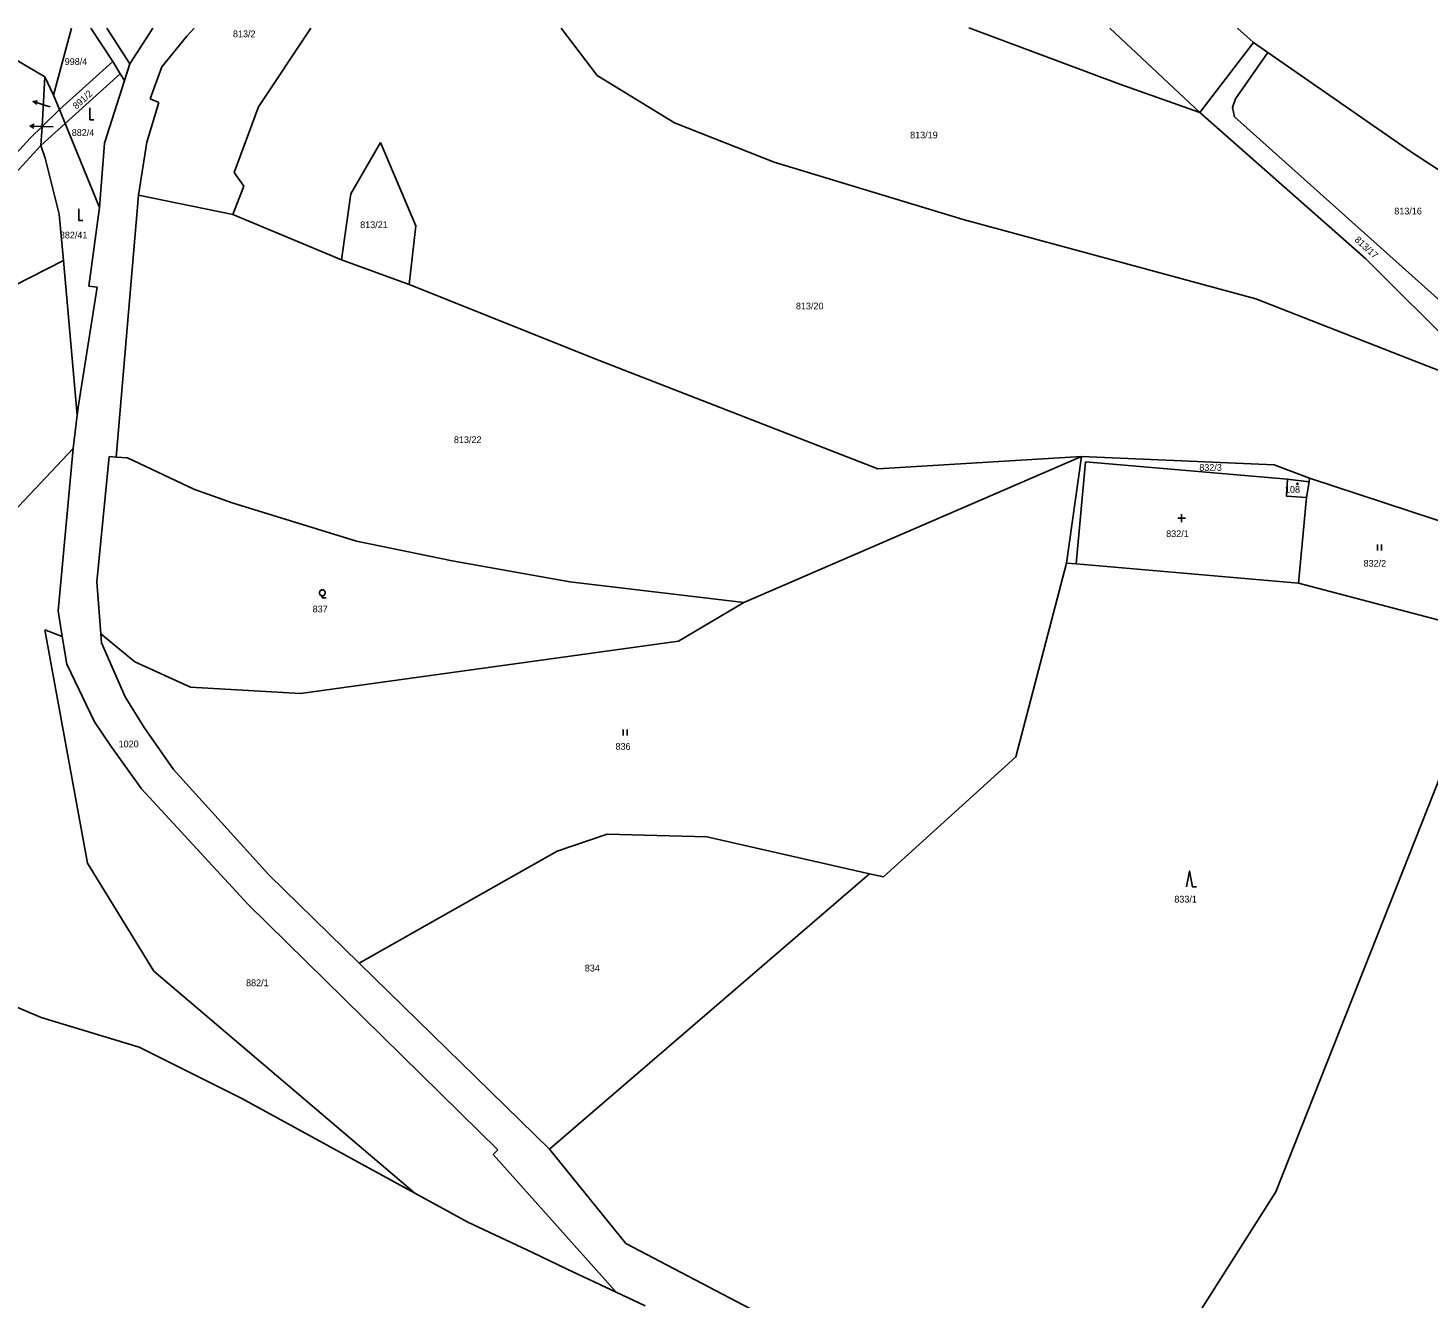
# Model space of a CAD drawing. Extents: x -801907 to -800293, y -1016964 to -1015684.
# Drawn here: x -801659.6 to -801306.6, y -1016005.6 to -1015685.2 of the extents above; entities that cross this region are included whole.
import ezdxf

# ---------------------------------------------------------------- set-up
doc = ezdxf.new("R2010")
doc.units = 0
for name, color, linetype in [('Default', 7, 'Continuous'), ('KN_HRANICE', 7, 'Continuous'), ('KN_KULTURY', 7, 'Continuous'), ('KN_PARCELY', 7, 'Continuous')]:
    doc.layers.add(name, color=color, linetype=linetype)

# ---------------------------------------------------------------- blocks, each defined once
blk = doc.blocks.new('302')
at = {"layer": 'Default'}
blk.add_lwpolyline([(0, 3), (0, 0), (1, 0)], dxfattribs=at)
blk = doc.blocks.new('305')
at = {"layer": 'Default'}
blk.add_lwpolyline([(0, 0.53), (-0.19, 0.53), (-0.53, 0.72), (-0.72, 1.06), (-0.72, 1.45), (-0.53, 1.79), (-0.19, 1.98), (0.2, 1.98), (0.54, 1.79), (0.73, 1.45), (0.73, 1.06), (0.54, 0.72), (0.2, 0.53), (0.01, 0.53), (0.01, 0), (1.01, 0)], dxfattribs=at)
blk = doc.blocks.new('306')
at = {"layer": 'Default'}
for p, q in [((-0.5, 1.5), (-0.5, 0)), ((0.5, 0), (0.5, 1.5))]:
    blk.add_line(p, q, dxfattribs=at)
blk = doc.blocks.new('308')
at = {"layer": 'Default'}
blk.add_lwpolyline([(-0.75, 0), (0, 4), (0.75, 0), (1.75, 0)], dxfattribs=at)
blk = doc.blocks.new('315')
at = {"layer": 'Default'}
for p, q in [((-1, 1), (1, 1)), ((0, 0), (0, 2))]:
    blk.add_line(p, q, dxfattribs=at)
blk = doc.blocks.new('10292')
at = {"layer": 'Default'}
blk.add_line((0, 3), (0, 0), dxfattribs=at)
blk.add_lwpolyline([(-0.5, 2), (0, 3), (0.5, 2)], dxfattribs=at)
blk = doc.blocks.new('402')
at = {"layer": 'Default'}
blk.add_lwpolyline([(0.09, 0.15), (0.18, 0), (0.09, -0.15), (-0.09, -0.15), (-0.18, 0), (-0.09, 0.15), (0.09, 0.15)], dxfattribs=at)

msp = doc.modelspace()

# ---------------------------------------------------------------- linework, layer by layer
at = {"layer": 'KN_HRANICE'}
for p, q in [((-801655.35, -1015697.53), (-801676.32, -1015685.21)), ((-801648.62, -1015685.21), (-801653.16, -1015702.14)), ((-801638.19, -1015693.68), (-801643.75, -1015685.21)), ((-801639.75, -1015685.21), (-801633.9, -1015694.23)), ((-801628.12, -1015685.21), (-801633.9, -1015694.23)), ((-801619.55, -1015687.28), (-801617.68, -1015685.21)), ((-801601.48, -1015705.1), (-801588.3, -1015685.21)), ((-801516.12, -1015697.22), (-801525.13, -1015685.21)), ((-801422.39, -1015685.21), (-801422.14, -1015685.28)), ((-801422.14, -1015685.28), (-801384.58, -1015699.28)), ((-801386.82, -1015685.21), (-801364.15, -1015706.53)), ((-801350.63, -1015688.84), (-801354.65, -1015685.21)), ((-801625.84, -1015695.02), (-801619.55, -1015687.28)), ((-801364.15, -1015706.53), (-801350.63, -1015688.84)), ((-801350.63, -1015688.84), (-801347.01, -1015691.35)), ((-801355.17, -1015703.07), (-801347.01, -1015691.35)), ((-801347.01, -1015691.35), (-801311.03, -1015716.36)), ((-801638.19, -1015693.68), (-801651.68, -1015705.75)), ((-801636.37, -1015696.73), (-801638.19, -1015693.68)), ((-801633.9, -1015694.23), (-801635.25, -1015698.47)), ((-801628.81, -1015703.03), (-801625.84, -1015695.02)), ((-801656.05, -1015710.04), (-801655.35, -1015697.53)), ((-801655.35, -1015697.53), (-801653.16, -1015702.14)), ((-801650.23, -1015709.31), (-801636.37, -1015696.73)), ((-801635.25, -1015698.47), (-801640.27, -1015714.25)), ((-801636.37, -1015696.73), (-801635.25, -1015698.47)), ((-801496.58, -1015709.13), (-801516.12, -1015697.22)), ((-801384.58, -1015699.28), (-801364.15, -1015706.53)), ((-801653.16, -1015702.14), (-801651.68, -1015705.75)), ((-801626.56, -1015704.02), (-801628.81, -1015703.03)), ((-801355.93, -1015705.28), (-801355.17, -1015703.07)), ((-801656.05, -1015710.04), (-801651.68, -1015705.75)), ((-801651.68, -1015705.75), (-801650.23, -1015709.31)), ((-801629.63, -1015714.03), (-801626.56, -1015704.02)), ((-801607.64, -1015721.66), (-801601.48, -1015705.1)), ((-801364.15, -1015706.53), (-801322.27, -1015743.39)), ((-801355.45, -1015707.64), (-801355.93, -1015705.28)), ((-801658.98, -1015712.93), (-801656.05, -1015710.04)), ((-801656.31, -1015714.79), (-801650.23, -1015709.31)), ((-801656.31, -1015714.79), (-801656.05, -1015710.04)), ((-801650.23, -1015709.31), (-801641.58, -1015730.49)), ((-801471.47, -1015719.01), (-801496.58, -1015709.13)), ((-801278.86, -1015776.11), (-801355.45, -1015707.64)), ((-801680.63, -1015736.45), (-801658.98, -1015712.93)), ((-801677.9, -1015738.17), (-801656.31, -1015714.79)), ((-801656.31, -1015714.79), (-801655.26, -1015718.04)), ((-801640.27, -1015714.25), (-801641.58, -1015730.49)), ((-801631.69, -1015727.32), (-801629.63, -1015714.03)), ((-801578.23, -1015727.02), (-801570.69, -1015714.08)), ((-801570.69, -1015714.08), (-801561.77, -1015735.11)), ((-801265.47, -1015746.32), (-801311.03, -1015716.36)), ((-801655.26, -1015718.04), (-801651.72, -1015732.13)), ((-801423.84, -1015733.52), (-801471.47, -1015719.01)), ((-801605.16, -1015725.05), (-801607.64, -1015721.66)), ((-801637.38, -1015793.41), (-801631.69, -1015727.32)), ((-801631.69, -1015727.32), (-801607.98, -1015732.2)), ((-801607.98, -1015732.2), (-801605.16, -1015725.05)), ((-801580.58, -1015743.62), (-801578.23, -1015727.02)), ((-801641.58, -1015730.49), (-801644.24, -1015750.29)), ((-801651.72, -1015732.13), (-801650.62, -1015743.8)), ((-801607.98, -1015732.2), (-801580.58, -1015743.62)), ((-801561.77, -1015735.11), (-801563.47, -1015749.83)), ((-801350.07, -1015753.47), (-801423.84, -1015733.52)), ((-801650.62, -1015743.8), (-801699.52, -1015768.78)), ((-801650.62, -1015743.8), (-801647.16, -1015782.83)), ((-801580.58, -1015743.62), (-801563.47, -1015749.83)), ((-801322.27, -1015743.39), (-801287.84, -1015777.83)), ((-801642.16, -1015750.56), (-801646.85, -1015780.3)), ((-801644.24, -1015750.29), (-801642.16, -1015750.56)), ((-801563.47, -1015749.83), (-801515.35, -1015769.14)), ((-801311.64, -1015768.49), (-801350.07, -1015753.47)), ((-801515.35, -1015769.14), (-801445.36, -1015796.31)), ((-801287.84, -1015777.83), (-801311.64, -1015768.49)), ((-801646.85, -1015780.3), (-801647.16, -1015782.83)), ((-801647.16, -1015782.83), (-801648.17, -1015791.2)), ((-801648.17, -1015791.2), (-801670.98, -1015815.34)), ((-801648.17, -1015791.2), (-801651.99, -1015832.14)), ((-801642.25, -1015824.81), (-801639.09, -1015793.23)), ((-801639.09, -1015793.23), (-801637.38, -1015793.41)), ((-801637.38, -1015793.41), (-801634.52, -1015793.59)), ((-801634.52, -1015793.59), (-801617.79, -1015801.46)), ((-801393.97, -1015793.22), (-801479.12, -1015830.07)), ((-801393.97, -1015793.22), (-801445.36, -1015796.31)), ((-801393.97, -1015793.22), (-801397.76, -1015820.1)), ((-801395.31, -1015820.31), (-801392.98, -1015794.6)), ((-801345.43, -1015795.33), (-801393.97, -1015793.22)), ((-801392.98, -1015794.6), (-801342.06, -1015798.94)), ((-801336.48, -1015798.73), (-801345.43, -1015795.33)), ((-801617.79, -1015801.46), (-801608.15, -1015804.9)), ((-801342.06, -1015798.94), (-801336.61, -1015799.6)), ((-801336.61, -1015799.6), (-801337.22, -1015803.55)), ((-801336.61, -1015799.6), (-801336.48, -1015798.73)), ((-801336.48, -1015798.73), (-801290.84, -1015813.7)), ((-801608.15, -1015804.9), (-801576.8, -1015814.54)), ((-801337.22, -1015803.55), (-801339.25, -1015825.17)), ((-801576.8, -1015814.54), (-801552.64, -1015819.52)), ((-801552.64, -1015819.52), (-801522.96, -1015824.79)), ((-801397.76, -1015820.1), (-801410.54, -1015868.95)), ((-801397.76, -1015820.1), (-801395.31, -1015820.31)), ((-801339.25, -1015825.17), (-801395.31, -1015820.31)), ((-801641.26, -1015837.91), (-801642.25, -1015824.81)), ((-801522.96, -1015824.79), (-801479.12, -1015830.07)), ((-801339.25, -1015825.17), (-801300.97, -1015835.22)), ((-801479.12, -1015830.07), (-801495.56, -1015839.77)), ((-801651.99, -1015832.14), (-801650.95, -1015838.61)), ((-801655.32, -1015836.89), (-801650.95, -1015838.61)), ((-801655.32, -1015836.89), (-801644.6, -1015895.74)), ((-801650.95, -1015838.61), (-801649.83, -1015845.59)), ((-801641.09, -1015840.21), (-801641.26, -1015837.91)), ((-801632.67, -1015845.03), (-801641.26, -1015837.91)), ((-801635.05, -1015853.84), (-801641.09, -1015840.21)), ((-801495.56, -1015839.77), (-801590.86, -1015852.95)), ((-801289.59, -1015838.57), (-801345.03, -1015978.6)), ((-801649.83, -1015845.59), (-801642.81, -1015860.14)), ((-801618.58, -1015851.35), (-801632.67, -1015845.03)), ((-801590.86, -1015852.95), (-801618.58, -1015851.35)), ((-801630.26, -1015861.51), (-801635.05, -1015853.84)), ((-801642.81, -1015860.14), (-801638.66, -1015866.37)), ((-801622.88, -1015872.13), (-801630.26, -1015861.51)), ((-801638.66, -1015866.37), (-801630.99, -1015877.01)), ((-801410.54, -1015868.95), (-801443.9, -1015899.19)), ((-801598.89, -1015898.65), (-801622.88, -1015872.13)), ((-801630.99, -1015877.01), (-801604.04, -1015906.13)), ((-801513.61, -1015888.43), (-801526.19, -1015892.72)), ((-801488.48, -1015889.13), (-801513.61, -1015888.43)), ((-801447.41, -1015898.4), (-801488.48, -1015889.13)), ((-801526.19, -1015892.72), (-801576.12, -1015920.96)), ((-801644.6, -1015895.74), (-801627.88, -1015922.95)), ((-801576.12, -1015920.96), (-801598.89, -1015898.65)), ((-801528.15, -1015967.86), (-801447.41, -1015898.4)), ((-801443.9, -1015899.19), (-801447.41, -1015898.4)), ((-801604.04, -1015906.13), (-801541.13, -1015968.05)), ((-801528.15, -1015967.86), (-801576.12, -1015920.96)), ((-801627.88, -1015922.95), (-801562.05, -1015978.96)), ((-801666.53, -1015930.26), (-801656.28, -1015934.67)), ((-801656.28, -1015934.67), (-801631.58, -1015942.12)), ((-801631.58, -1015942.12), (-801605.65, -1015955.07)), ((-801605.65, -1015955.07), (-801562.05, -1015978.96)), ((-801541.13, -1015968.05), (-801542.3, -1015969.22)), ((-801528.15, -1015967.86), (-801508.87, -1015991.61)), ((-801542.3, -1015969.22), (-801511.29, -1016003.9)), ((-801345.03, -1015978.6), (-801393.03, -1016054.26)), ((-801562.05, -1015978.96), (-801548.67, -1015986.29)), ((-801548.67, -1015986.29), (-801532.43, -1015993.94)), ((-801508.87, -1015991.61), (-801415.39, -1016040.55)), ((-801532.43, -1015993.94), (-801523.47, -1015998.16)), ((-801523.47, -1015998.16), (-801511.29, -1016003.9)), ((-801511.29, -1016003.9), (-801503.99, -1016007.34))]:
    msp.add_line(p, q, dxfattribs=at)
msp.add_lwpolyline([(-801342.06, -1015798.94), (-801342.33, -1015803.19), (-801337.22, -1015803.55)], dxfattribs=at)
at = {"layer": 'KN_PARCELY'}
for p, q in [((-801654, -1015705.06), (-801655.42, -1015704.63)), ((-801653.28, -1015710.13), (-801656.06, -1015710.04))]:
    msp.add_line(p, q, dxfattribs=at)

# ---------------------------------------------------------------- block references
at = {"layer": 'KN_KULTURY'}
for name, p in [('302', (-801643.98, -1015708.35)), ('302', (-801646.76, -1015733.76)), ('402', (-801339.56, -1015800.12)), ('315', (-801368.74, -1015809.8)), ('306', (-801318.86, -1015816.94)), ('305', (-801585.4, -1015828.86)), ('306', (-801509.04, -1015863.55)), ('308', (-801366.75, -1015901.74))]:
    msp.add_blockref(name, p, dxfattribs=at)
at = {"layer": 'KN_PARCELY'}
for p, rotation in [((-801655.42, -1015704.63), 72.994823), ((-801656.06, -1015710.04), 88.2355)]:
    msp.add_blockref('10292', p, dxfattribs=dict(at, rotation=rotation))

# ---------------------------------------------------------------- texts
for s, height, p in [('813/2', 1.7, (-801607.91, -1015687.54)), ('998/4', 1.7, (-801650.34, -1015694.52)), ('998/1', 0.1, (-801654.23, -1015705.06)), ('891/6', 0.1, (-801653.52, -1015710.13)), ('882/4', 1.7, (-801648.56, -1015712.42)), ('813/19', 1.7, (-801437.19, -1015713.03)), ('813/16', 1.7, (-801315.13, -1015732.22)), ('813/21', 1.7, (-801575.84, -1015735.66)), ('882/41', 1.7, (-801651.57, -1015738.26)), ('813/20', 1.7, (-801465.99, -1015756.14)), ('813/22', 1.7, (-801552.21, -1015789.85)), ('832/3', 1.7, (-801364.29, -1015796.84)), ('108', 1.7, (-801342.69, -1015802.37)), ('832/1', 1.7, (-801372.63, -1015813.54)), ('832/2', 1.7, (-801322.88, -1015821.01)), ('837', 1.7, (-801587.83, -1015832.53)), ('1020', 1.7, (-801636.74, -1015866.55)), ('836', 1.7, (-801511.47, -1015867.16)), ('833/1', 1.7, (-801370.58, -1015905.67)), ('834', 1.7, (-801519.21, -1015923.05)), ('882/1', 1.7, (-801604.61, -1015926.77))]:
    msp.add_text(s, height=height, dxfattribs=at).set_placement(p)
for s, rotation, p in [('891/2', 42.227, (-801647.38, -1015705.81)), ('813/17', 317.476, (-801325.26, -1015738.8))]:
    msp.add_text(s, height=1.7, rotation=rotation, dxfattribs=at).set_placement(p)

doc.saveas('drawing.dxf')
